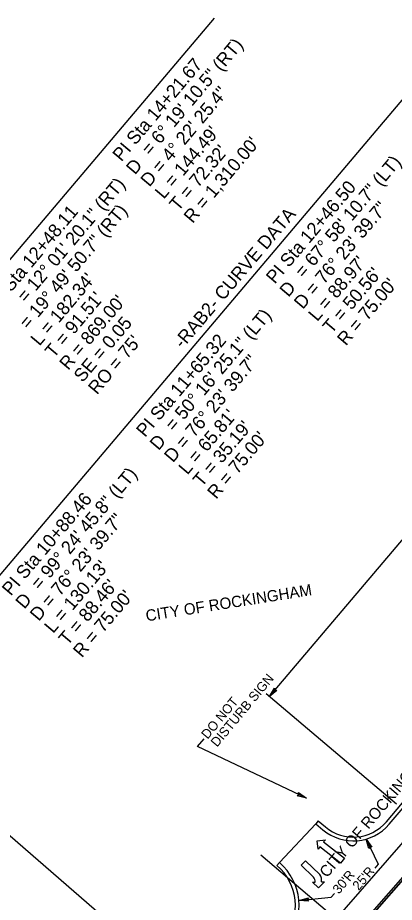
# Model space of a CAD drawing. Extents: x 1761082 to 1764358, y 421907 to 425434.
# Drawn here: x 1762877.9 to 1763077.8, y 424026 to 424495.2 of the extents above; entities that cross this region are included whole.
import ezdxf

# ---------------------------------------------------------------- set-up
doc = ezdxf.new("R2010")
doc.units = 0
for name, color, linetype in [('MARK LEFT TURN ARROW CELL', 7, 'Continuous'), ('MARK UTURN ARROW CELL', 7, 'Continuous'), ('Prop Mkg Skp Wht', 7, 'Continuous'), ('Prop Mkg Solid White Diagonals', 7, 'Continuous'), ('Prop Mkg Solid White Lane Line', 7, 'Continuous'), ('Prop Mkg Solid White Multiple Diagonals V8i', 7, 'Continuous'), ('Prop Mkg Solid Yel Skip LT', 7, 'Continuous'), ('Prop Mkg Solid Yel Skip RT', 7, 'Continuous'), ('Prop Mkg Solid Yellow Diagonals', 7, 'Continuous'), ('Prop Mkg Solid Yellow Edge Line', 7, 'Continuous'), ('Prop Mkg Solid Yellow Lane Line', 7, 'Continuous'), ('Prop Mkr Yel 40ft Spc', 7, 'Continuous'), ('Scratch_Level_0', 7, 'Continuous')]:
    doc.layers.add(name, color=color, linetype=linetype)

msp = doc.modelspace()

# ---------------------------------------------------------------- linework, layer by layer
at = {"layer": 'MARK LEFT TURN ARROW CELL'}
for p, q in [((1763073.53, 424068.75), (1763326.74, 424367.65)), ((1763037.35, 424069.23), (1763036.06, 424067.7)), ((1763037.35, 424069.23), (1763041.17, 424066.02)), ((1763015.46, 424045.54), (1763016.76, 424047.06))]:
    msp.add_line(p, q, dxfattribs=at)
for centre, radius, start, end in [((1763055.98, 424083.62), 23, 229.9083, 319.7301), ((1762997.25, 424024.27), 28, 322.2701, 49.4412)]:
    msp.add_arc(centre, radius, start, end, dxfattribs=at)
at = {"layer": 'MARK UTURN ARROW CELL'}
for p, q in [((1762863.58, 424193.79), (1763141.97, 424522.4)), ((1762717.84, 424182.78), (1762982.36, 424495.02))]:
    msp.add_line(p, q, dxfattribs=at)
msp.add_lwpolyline([(1763013.15, 423940.16), (1762869.88, 424064.58), (1762781.79, 423960.6)], dxfattribs=at)
at = {"layer": 'Prop Mkg Skp Wht'}
for p, q in [((1763075.05, 424067.46), (1763328.27, 424366.36)), ((1763016.76, 424047.06), (1763036.06, 424067.7)), ((1763036.06, 424067.7), (1763039.88, 424064.49))]:
    msp.add_line(p, q, dxfattribs=at)
for centre, radius, start, end in [((1763055.98, 424083.62), 25, 229.9083, 319.7301), ((1762997.25, 424024.27), 30, 322.2701, 49.4412)]:
    msp.add_arc(centre, radius, start, end, dxfattribs=at)
at = {"layer": 'Prop Mkg Solid White Diagonals'}
msp.add_line((1763090.51, 424047.41), (1762859.56, 423783.42), dxfattribs=at)
at = {"layer": 'Prop Mkg Solid White Lane Line'}
msp.add_line((1762859.56, 423783.42), (1763090.51, 424047.41), dxfattribs=at)
at = {"layer": 'Prop Mkg Solid White Multiple Diagonals V8i'}
msp.add_line((1763006.96, 424051.12), (1763119.33, 423955.94), dxfattribs=at)
at = {"layer": 'Prop Mkg Solid Yel Skip RT'}
for p, q in [((1763011.48, 424135.11), (1763231.9, 424395.3)), ((1763078.89, 424078.01), (1763009.69, 424136.63))]:
    msp.add_line(p, q, dxfattribs=at)
for points in [[(1763031.17, 424081.2), (1762973.31, 424108.6), (1762976.8, 424112.73)], [(1763062.76, 424059.56), (1763069.26, 424046.3), (1763067.37, 424044.08)], [(1763027.13, 424026.99), (1763044.29, 424028.78), (1763045.95, 424030.73)]]:
    msp.add_lwpolyline(points, dxfattribs=at)
at = {"layer": 'Prop Mkg Solid Yellow Diagonals'}
for p, q in [((1763036.72, 424058.62), (1763041.18, 424059.2)), ((1763041.18, 424059.2), (1763040.25, 424058.02)), ((1763037.29, 424054.24), (1763036.72, 424058.62)), ((1763038.21, 424055.42), (1763037.29, 424054.24)), ((1763049.23, 424046.79), (1763038.21, 424055.42)), ((1763040.25, 424058.02), (1763051.27, 424049.38)), ((1763028.29, 424045.74), (1763030.6, 424048.1)), ((1763034.83, 424039.34), (1763028.29, 424045.74)), ((1763030.6, 424048.1), (1763038.14, 424040.71)), ((1763051.27, 424049.38), (1763049.23, 424046.79)), ((1763034.32, 424036.75), (1763035.81, 424036.76)), ((1763037.57, 424033.64), (1763034.32, 424036.75)), ((1763040.62, 424036.81), (1763037.57, 424033.64)), ((1763039.13, 424036.8), (1763040.62, 424036.81))]:
    msp.add_line(p, q, dxfattribs=at)
for centre, radius, start, end in [((1763033.95, 424037.57), 5.25, 351.5937, 36.9054), ((1763032.55, 424037), 3.27, 355.9233, 45.5815)]:
    msp.add_arc(centre, radius, start, end, dxfattribs=at)
at = {"layer": 'Prop Mkg Solid Yellow Edge Line'}
msp.add_line((1762898.9, 423848.13), (1763091.01, 424067.73), dxfattribs=at)
at = {"layer": 'Prop Mkg Solid Yellow Lane Line'}
for points in [[(1763015.45, 424138.44), (1763011.48, 424135.11), (1763014.1, 424139.61), (1763014.37, 424138.53)], [(1763026.94, 424084.18), (1763031.17, 424081.2), (1763026.15, 424082.58), (1763027.12, 424083.12)], [(1763064.22, 424054.59), (1763062.76, 424059.56), (1763065.83, 424055.35), (1763064.73, 424055.53)], [(1763032.29, 424026.65), (1763027.13, 424026.99), (1763032.14, 424028.42), (1763031.58, 424027.46)]]:
    msp.add_lwpolyline(points, close=True, dxfattribs=at)
at = {"layer": 'Scratch_Level_0'}
msp.add_line((1762858.8, 423784.07), (1763100.11, 424059.9), dxfattribs=at)

# ---------------------------------------------------------------- texts
at = {"layer": 'Prop Mkg Solid Yel Skip LT'}
for s, height, rotation, p in [('CITY OF ROCKINGHAM', 6, 9.0063, (1762946.3, 424175)), ('DISTURB SIGN', 5, 50.1302, (1762983.68, 424108.04)), ('DO NOT', 5, 50.1302, (1762978.65, 424112.24)), ('CITY OF ROCKINGHAM', 6, 49.5522, (1763042.01, 424038.68)), ("30'R", 5, 49.7301, (1763048.33, 424030.07)), ("25'R", 5, 49.7301, (1763058.88, 424032.01))]:
    msp.add_text(s, height=height, rotation=rotation, dxfattribs=at).set_placement(p)
at = {"layer": 'Prop Mkr Yel 40ft Spc'}
for s, rotation, p in [('= 6%%d 19\' 10.5" (RT)', 49.875, (1762948.17, 424421.55)), ('PI Sta 14+21.67', 49.875, (1762932.91, 424418.49)), ('D = 4%%d 22\' 25.4"', 49.875, (1762947.77, 424405.09)), ("L = 144.49'", 49.875, (1762955.41, 424398.64)), ("R = 1,310.00'", 49.875, (1762970.7, 424385.75)), ("T = 72.32'", 49.875, (1762963.06, 424392.2)), ('= 67%%d 58\' 10.7" (LT)', 49.7691, (1763029.63, 424356.64)), ('D', 49.875, (1762940.12, 424411.53)), ('= 12%%d 01\' 20.1" (RT)', 49.8337, (1762882.19, 424343.65)), ('PI Sta 12+46.50', 49.7691, (1763014.36, 424353.61)), ('D = 76%%d 23\' 39.7"', 49.7691, (1763029.19, 424340.18)), ('PI Sta 12+48.11', 49.8337, (1762866.92, 424340.6)), ('= 19%%d 49\' 50.7" (RT)', 49.8337, (1762883.38, 424329.56)), ('-RAB2- CURVE DATA', 49.7301, (1762965.4, 424319.33)), ("L = 88.97'", 49.7691, (1763036.83, 424333.72)), ("L = 182.34'", 49.8337, (1762889.41, 424320.74)), ("T = 50.56'", 49.7691, (1763044.46, 424327.26)), ('D', 49.7691, (1763021.56, 424346.64)), ("R = 75.00'", 49.7691, (1763052.09, 424320.8)), ("T = 91.51'", 49.8337, (1762897.06, 424314.29)), ("R = 869.00'", 49.8337, (1762904.7, 424307.84)), ('SE = 0.05', 49.8337, (1762912.33, 424301.38)), ('= 50%%d 16\' 25.1" (LT)', 49.7691, (1762960.73, 424275.31)), ("RO = 75'", 49.8337, (1762919.96, 424294.91)), ('PI Sta 11+65.32', 49.7691, (1762945.46, 424272.28)), ('D = 76%%d 23\' 39.7"', 49.7691, (1762960.29, 424258.85)), ("L = 65.81'", 49.7691, (1762967.92, 424252.39)), ("T = 35.19'", 49.7691, (1762975.56, 424245.93)), ("R = 75.00'", 49.7691, (1762983.19, 424239.47)), ('D', 49.7691, (1762952.65, 424265.3)), ('= 99%%d 24\' 45.8" (LT)', 49.7691, (1762889.48, 424191.2)), ('PI Sta 10+88.46', 49.7691, (1762874.21, 424188.17)), ('D = 76%%d 23\' 39.7"', 49.7691, (1762889.04, 424174.74)), ("L = 130.13'", 49.7691, (1762896.68, 424168.28)), ("T = 88.46'", 49.7691, (1762904.31, 424161.83)), ("R = 75.00'", 49.7691, (1762911.94, 424155.37)), ('D', 49.7691, (1762881.41, 424181.2))]:
    msp.add_text(s, height=7, rotation=rotation, dxfattribs=at).set_placement(p)

doc.saveas('drawing.dxf')
